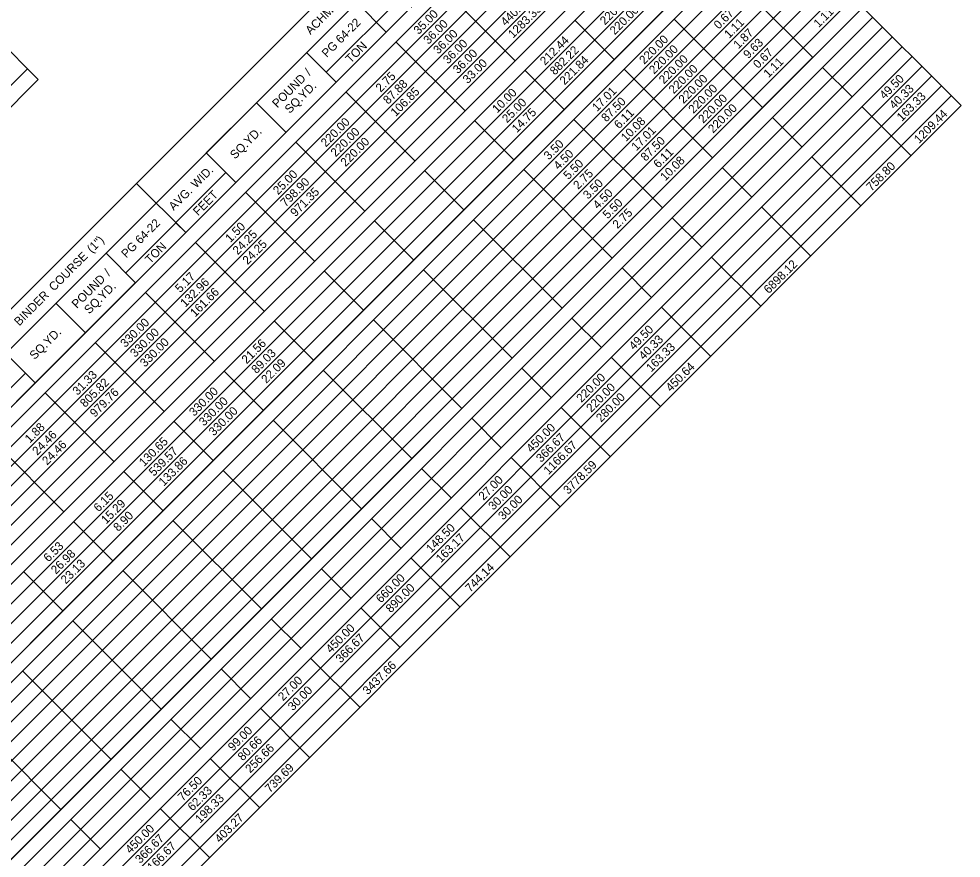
# Model space of a CAD drawing. Extents: x 1675667 to 1681231, y 227227 to 232694.
# Drawn here: x 1679139 to 1679800, y 230278 to 230867 of the extents above; entities that cross this region are included whole.
import ezdxf

# ---------------------------------------------------------------- set-up
doc = ezdxf.new("R2010")
doc.units = 0
doc.layers.add('Default', color=7, linetype='Continuous')

msp = doc.modelspace()

# ---------------------------------------------------------------- linework, layer by layer
at = {"layer": 'Default'}
for p, q in [((1678525.01, 230054.56), (1679538.35, 231068.14)), ((1679800.36, 230806.19), (1679538.35, 231068.14)), ((1679800.36, 230806.19), (1679538.35, 231068.14)), ((1678778.69, 230280.72), (1679552.14, 231054.36)), ((1678559.49, 230020.09), (1679572.82, 231033.68)), ((1678566.38, 230013.2), (1679579.72, 231026.78)), ((1678573.28, 230006.31), (1679586.61, 231019.89)), ((1678580.17, 229999.41), (1679593.51, 231013)), ((1678587.07, 229992.52), (1679600.4, 231006.1)), ((1678593.96, 229985.63), (1679607.3, 230999.21)), ((1678600.86, 229978.73), (1679614.2, 230992.32)), ((1678607.75, 229971.84), (1679621.09, 230985.42)), ((1678614.65, 229964.94), (1679627.99, 230978.53)), ((1678614.65, 229964.94), (1679627.99, 230978.53)), ((1678621.54, 229958.05), (1679634.88, 230971.64)), ((1678628.44, 229951.16), (1679641.78, 230964.74)), ((1678635.33, 229944.26), (1679648.67, 230957.85)), ((1678642.23, 229937.37), (1679655.57, 230950.96)), ((1678649.12, 229930.48), (1679662.46, 230944.06)), ((1678656.02, 229923.58), (1679669.36, 230937.17)), ((1678662.91, 229916.69), (1679676.25, 230930.28)), ((1678669.81, 229909.8), (1679683.15, 230923.38)), ((1678676.71, 229902.9), (1679690.04, 230916.49)), ((1678683.6, 229896.01), (1679696.94, 230909.6)), ((1678690.5, 229889.12), (1679703.83, 230902.7)), ((1679696.26, 230839.96), (1679634.2, 230902)), ((1679696.26, 230839.96), (1679634.2, 230902)), ((1678697.39, 229882.22), (1679710.73, 230895.81)), ((1679354.99, 230829.58), (1679425.3, 230899.91)), ((1678704.29, 229875.33), (1679717.62, 230888.92)), ((1679152.98, 230824.49), (1679082.99, 230894.46)), ((1679152.98, 230824.49), (1679082.99, 230894.46)), ((1679291.57, 230752.36), (1679432.2, 230893.02)), ((1678711.18, 229868.44), (1679724.52, 230882.02)), ((1679487.36, 230837.87), (1679439.09, 230886.12)), ((1679487.36, 230837.87), (1679439.09, 230886.12)), ((1679397.04, 230857.85), (1679376.36, 230878.53)), ((1678718.08, 229861.54), (1679731.41, 230875.13)), ((1679556.99, 230838.57), (1679592.15, 230873.73)), ((1679661.1, 230804.8), (1679731.41, 230875.13)), ((1678724.97, 229854.65), (1679738.31, 230868.24)), ((1679397.04, 230857.85), (1679390.15, 230864.75)), ((1679556.99, 230838.57), (1679529.41, 230866.14)), ((1679556.99, 230838.57), (1679529.41, 230866.14)), ((1679661.1, 230804.8), (1679599.04, 230866.84)), ((1679661.1, 230804.8), (1679599.04, 230866.84)), ((1678731.87, 229847.76), (1679745.2, 230861.34)), ((1678738.76, 229840.86), (1679752.1, 230854.45)), ((1679452.2, 230802.7), (1679403.94, 230850.96)), ((1679452.2, 230802.7), (1679403.94, 230850.96)), ((1678745.66, 229833.97), (1679758.99, 230847.55)), ((1678745.66, 229833.97), (1679758.99, 230847.55)), ((1679361.88, 230822.69), (1679341.2, 230843.37)), ((1678752.55, 229827.08), (1679765.89, 230840.66)), ((1679521.83, 230803.4), (1679556.99, 230838.57)), ((1678759.45, 229820.18), (1679772.78, 230833.77)), ((1678793.82, 230480.42), (1679145.39, 230832.07)), ((1679521.83, 230803.4), (1679494.25, 230830.98)), ((1679521.83, 230803.4), (1679494.25, 230830.98)), ((1679625.94, 230769.63), (1679563.89, 230831.67)), ((1679625.94, 230769.63), (1679563.89, 230831.67)), ((1679723.84, 230812.39), (1679703.15, 230833.07)), ((1679723.84, 230812.39), (1679703.15, 230833.07)), ((1678766.34, 229813.29), (1679779.68, 230826.87)), ((1678801.41, 230472.84), (1679152.98, 230824.49)), ((1678773.24, 229806.4), (1679786.57, 230819.98)), ((1679417.05, 230767.54), (1679368.78, 230815.79)), ((1679417.05, 230767.54), (1679368.78, 230815.79)), ((1678780.13, 229799.5), (1679793.47, 230813.09)), ((1678787.03, 229792.61), (1679800.36, 230806.19)), ((1679270.89, 230773.04), (1679306.04, 230808.2)), ((1679326.73, 230787.52), (1679306.04, 230808.2)), ((1679486.68, 230768.24), (1679521.83, 230803.4)), ((1679625.94, 230769.63), (1679661.1, 230804.8)), ((1679765.21, 230771.03), (1679730.73, 230805.5)), ((1679765.21, 230771.03), (1679730.73, 230805.5)), ((1679590.79, 230734.47), (1679528.73, 230796.51)), ((1679590.79, 230734.47), (1679528.73, 230796.51)), ((1679688.68, 230777.22), (1679667.99, 230797.9)), ((1679688.68, 230777.22), (1679667.99, 230797.9)), ((1679486.68, 230768.24), (1679459.1, 230795.81)), ((1679486.68, 230768.24), (1679459.1, 230795.81)), ((1679381.89, 230732.37), (1679333.62, 230780.63)), ((1679381.89, 230732.37), (1679333.62, 230780.63)), ((1679291.57, 230752.36), (1679270.89, 230773.04)), ((1679590.79, 230734.47), (1679625.94, 230769.63)), ((1679730.05, 230735.86), (1679695.57, 230770.33)), ((1679730.05, 230735.86), (1679695.57, 230770.33)), ((1679451.52, 230733.07), (1679486.68, 230768.24)), ((1679214.36, 230688.92), (1679284.68, 230759.25)), ((1679291.57, 230752.36), (1679284.68, 230759.25)), ((1679451.52, 230733.07), (1679423.94, 230760.65)), ((1679451.52, 230733.07), (1679423.94, 230760.65)), ((1679555.63, 230699.3), (1679493.57, 230761.34)), ((1679555.63, 230699.3), (1679493.57, 230761.34)), ((1679653.52, 230742.06), (1679632.84, 230762.74)), ((1679653.52, 230742.06), (1679632.84, 230762.74)), ((1679150.95, 230611.7), (1679291.57, 230752.36)), ((1679235.73, 230737.87), (1679221.94, 230751.66)), ((1679256.42, 230717.19), (1679221.94, 230751.66)), ((1679346.73, 230697.21), (1679298.47, 230745.46)), ((1679346.73, 230697.21), (1679298.47, 230745.46)), ((1679170.27, 230451.75), (1679451.52, 230733.07)), ((1679555.63, 230699.3), (1679590.79, 230734.47)), ((1679694.89, 230700.7), (1679660.42, 230735.17)), ((1679694.89, 230700.7), (1679660.42, 230735.17)), ((1679256.42, 230717.19), (1679249.52, 230724.08)), ((1679416.36, 230697.91), (1679388.78, 230725.48)), ((1679416.36, 230697.91), (1679388.78, 230725.48)), ((1679520.47, 230664.14), (1679458.42, 230726.18)), ((1679520.47, 230664.14), (1679458.42, 230726.18)), ((1679618.37, 230706.89), (1679597.68, 230727.57)), ((1679618.37, 230706.89), (1679597.68, 230727.57)), ((1679311.58, 230662.04), (1679263.31, 230710.3)), ((1679311.58, 230662.04), (1679263.31, 230710.3)), ((1679221.26, 230682.03), (1679200.57, 230702.71)), ((1679520.47, 230664.14), (1679555.63, 230699.3)), ((1679659.74, 230665.53), (1679625.26, 230700)), ((1679659.74, 230665.53), (1679625.26, 230700)), ((1679381.21, 230662.74), (1679353.63, 230690.32)), ((1679381.21, 230662.74), (1679353.63, 230690.32)), ((1679485.32, 230628.97), (1679423.26, 230691.01)), ((1679485.32, 230628.97), (1679423.26, 230691.01)), ((1679583.21, 230671.73), (1679562.52, 230692.41)), ((1679583.21, 230671.73), (1679562.52, 230692.41)), ((1679276.42, 230626.88), (1679228.15, 230675.13)), ((1679276.42, 230626.88), (1679228.15, 230675.13)), ((1679186.1, 230646.86), (1679165.42, 230667.54)), ((1679415, 230558.64), (1679520.47, 230664.14)), ((1679624.58, 230630.37), (1679590.11, 230664.84)), ((1679624.58, 230630.37), (1679590.11, 230664.84)), ((1679548.05, 230636.56), (1679527.37, 230657.24)), ((1679548.05, 230636.56), (1679527.37, 230657.24)), ((1679346.05, 230627.58), (1679318.47, 230655.15)), ((1679346.05, 230627.58), (1679318.47, 230655.15)), ((1679450.16, 230593.81), (1679388.1, 230655.85)), ((1679450.16, 230593.81), (1679388.1, 230655.85)), ((1679241.26, 230591.71), (1679193, 230639.97)), ((1679241.26, 230591.71), (1679193, 230639.97)), ((1679150.95, 230611.7), (1679130.26, 230632.38)), ((1679589.42, 230595.2), (1679554.95, 230629.67)), ((1679589.42, 230595.2), (1679554.95, 230629.67)), ((1679108.89, 230583.42), (1679144.05, 230618.59)), ((1679150.95, 230611.7), (1679144.05, 230618.59)), ((1679310.9, 230592.41), (1679283.31, 230619.98)), ((1679310.9, 230592.41), (1679283.31, 230619.98)), ((1679415, 230558.64), (1679352.95, 230620.68)), ((1679415, 230558.64), (1679352.95, 230620.68)), ((1679512.9, 230601.4), (1679492.21, 230622.08)), ((1679512.9, 230601.4), (1679492.21, 230622.08)), ((1679045.48, 230506.2), (1679150.95, 230611.7)), ((1679206.11, 230556.55), (1679157.84, 230604.8)), ((1679206.11, 230556.55), (1679157.84, 230604.8)), ((1679554.27, 230560.04), (1679519.79, 230594.5)), ((1679554.27, 230560.04), (1679519.79, 230594.5)), ((1679275.74, 230557.25), (1679248.16, 230584.82)), ((1679275.74, 230557.25), (1679248.16, 230584.82)), ((1679379.85, 230523.48), (1679317.79, 230585.52)), ((1679379.85, 230523.48), (1679317.79, 230585.52)), ((1679477.74, 230566.23), (1679457.05, 230586.91)), ((1679477.74, 230566.23), (1679457.05, 230586.91)), ((1679170.95, 230521.38), (1679122.68, 230569.64)), ((1679170.95, 230521.38), (1679122.68, 230569.64)), ((1679379.85, 230523.48), (1679415, 230558.64)), ((1679519.11, 230524.87), (1679484.64, 230559.34)), ((1679519.11, 230524.87), (1679484.64, 230559.34)), ((1679442.58, 230531.07), (1679421.9, 230551.75)), ((1679442.58, 230531.07), (1679421.9, 230551.75)), ((1679240.58, 230522.08), (1679213, 230549.65)), ((1679240.58, 230522.08), (1679213, 230549.65)), ((1679344.69, 230488.31), (1679282.63, 230550.35)), ((1679344.69, 230488.31), (1679282.63, 230550.35)), ((1679274.38, 230417.98), (1679379.85, 230523.48)), ((1679483.95, 230489.71), (1679449.48, 230524.17)), ((1679483.95, 230489.71), (1679449.48, 230524.17)), ((1679205.43, 230486.92), (1679177.85, 230514.49)), ((1679205.43, 230486.92), (1679177.85, 230514.49)), ((1679309.53, 230453.15), (1679247.48, 230515.19)), ((1679309.53, 230453.15), (1679247.48, 230515.19)), ((1679407.43, 230495.9), (1679386.74, 230516.58)), ((1679407.43, 230495.9), (1679386.74, 230516.58)), ((1679448.8, 230454.54), (1679414.32, 230489.01)), ((1679448.8, 230454.54), (1679414.32, 230489.01)), ((1679170.27, 230451.75), (1679142.69, 230479.32)), ((1679170.27, 230451.75), (1679142.69, 230479.32)), ((1679274.38, 230417.98), (1679212.32, 230480.02)), ((1679274.38, 230417.98), (1679212.32, 230480.02)), ((1679372.27, 230460.74), (1679351.59, 230481.42)), ((1679372.27, 230460.74), (1679351.59, 230481.42)), ((1679406.75, 230426.27), (1679379.17, 230453.84)), ((1679406.75, 230426.27), (1679379.17, 230453.84)), ((1678959.33, 230240.76), (1679170.27, 230451.75)), ((1679337.11, 230425.57), (1679316.43, 230446.25)), ((1679337.11, 230425.57), (1679316.43, 230446.25)), ((1679239.22, 230382.82), (1679177.16, 230444.86)), ((1679239.22, 230382.82), (1679177.16, 230444.86)), ((1679168.91, 230312.49), (1679274.38, 230417.98)), ((1679378.48, 230384.21), (1679344.01, 230418.68)), ((1679378.48, 230384.21), (1679344.01, 230418.68)), ((1679204.06, 230347.65), (1679142.01, 230409.69)), ((1679204.06, 230347.65), (1679142.01, 230409.69)), ((1679301.96, 230390.41), (1679281.27, 230411.09)), ((1679301.96, 230390.41), (1679281.27, 230411.09)), ((1679343.33, 230349.05), (1679308.85, 230383.51)), ((1679343.33, 230349.05), (1679308.85, 230383.51)), ((1679168.91, 230312.49), (1679106.85, 230374.53)), ((1679168.91, 230312.49), (1679106.85, 230374.53)), ((1679266.8, 230355.24), (1679246.12, 230375.92)), ((1679266.8, 230355.24), (1679246.12, 230375.92)), ((1679308.17, 230313.88), (1679273.7, 230348.35)), ((1679308.17, 230313.88), (1679273.7, 230348.35)), ((1679231.64, 230320.08), (1679210.96, 230340.76)), ((1679231.64, 230320.08), (1679210.96, 230340.76)), ((1679133.75, 230277.32), (1679168.91, 230312.49)), ((1679273.02, 230278.72), (1679238.54, 230313.18)), ((1679273.02, 230278.72), (1679238.54, 230313.18)), ((1679196.49, 230284.91), (1679175.8, 230305.59)), ((1679196.49, 230284.91), (1679175.8, 230305.59))]:
    msp.add_line(p, q, dxfattribs=at)

# ---------------------------------------------------------------- texts
for s, p in [('440.00', (1679480.9, 230861.64)), ('220.00', (1679550.54, 230862.34)), ('ACHM', (1679343.96, 230855.67)), ('1283.33', (1679486.14, 230853.1)), ('220.00', (1679557.43, 230855.45)), ('35.00', (1679419.81, 230855.7)), ('0.67', (1679630.35, 230859.43)), ('1.11', (1679700.39, 230860.54)), (' 64-22', (1679363.65, 230847.79)), ('36.00', (1679426.71, 230848.81)), ('1.11', (1679637.66, 230852.95)), ('36.00', (1679433.6, 230841.91)), ('220.00', (1679578.12, 230834.77)), ('1.87', (1679644.14, 230845.65)), ('PG', (1679355.44, 230839.58)), ('TON', (1679372.12, 230835.57)), ('36.00', (1679440.5, 230835.02)), ('212.44', (1679508.49, 230834.07)), ('9.63', (1679651.04, 230838.75)), ('36.00', (1679447.39, 230828.13)), ('882.22', (1679515.39, 230827.19)), ('220.00', (1679585.01, 230827.88)), ('0.67', (1679657.93, 230831.86)), ('33.00', (1679454.29, 230821.23)), ('221.84', (1679522.28, 230820.29)), ('220.00', (1679591.91, 230820.98)), ('1.11', (1679665.24, 230825.38)), (' /', (1679341.81, 230825.41)), ('2.75', (1679393.18, 230815.27)), ('220.00', (1679598.8, 230814.09)), ('POUND', (1679320.7, 230804.3)), ('87.88', (1679398.44, 230806.74)), ('220.00', (1679605.7, 230807.2)), ('49.50', (1679746.61, 230810.24)), ('SQ.YD.', (1679329.43, 230800.3)), ('106.85', (1679403.67, 230798.18)), ('10.00', (1679474.97, 230800.55)), ('17.01', (1679545.01, 230801.65)), ('220.00', (1679612.59, 230800.3)), ('40.33', (1679753.5, 230803.34)), ('25.00', (1679481.87, 230793.66)), ('87.50', (1679551.5, 230794.36)), ('220.00', (1679619.49, 230793.41)), ('163.33', (1679758.74, 230794.8)), ('14.75', (1679488.74, 230786.74)), ('6.11', (1679560.45, 230789.52)), ('220.00', (1679626.38, 230786.51)), ('1209.44', (1679770.82, 230779.3)), ('220.00', (1679354.75, 230776.83)), ('10.08', (1679565.28, 230780.56)), ('220.00', (1679361.64, 230769.94)), ('17.01', (1679572.59, 230774.08)), ('SQ.YD.', (1679291.09, 230768.31)), ('220.00', (1679368.54, 230763.04)), ('87.50', (1679579.08, 230766.78)), ('3.50', (1679511.1, 230767.73)), ('4.50', (1679517.99, 230760.84)), ('6.11', (1679588.03, 230761.94)), ('10.08', (1679592.86, 230752.99)), ('5.50', (1679524.89, 230753.95)), ('758.80', (1679737.39, 230745.86)), (' WID.', (1679262.16, 230746.28)), ('25.00', (1679321.24, 230743.31)), ('2.75', (1679531.76, 230747.03)), ('798.90', (1679326.49, 230734.77)), ('3.50', (1679538.68, 230740.16)), ('AVG.', (1679248.08, 230732.19)), ('FEET', (1679265.15, 230728.58)), ('971.35', (1679333.36, 230727.85)), ('4.50', (1679545.57, 230733.27)), ('5.50', (1679552.47, 230726.37)), ('2.75', (1679559.34, 230719.46)), (' 64-22', (1679223.02, 230707.13)), ('1.50', (1679287.73, 230709.79)), ('24.25', (1679292.95, 230701.23)), (' (1")', (1679189.15, 230700.83)), ('PG', (1679214.82, 230698.92)), ('TON', (1679231.49, 230694.91)), ('24.25', (1679299.85, 230694.34)), (' COURSE', (1679162.44, 230674.11)), ('6898.12', (1679665.43, 230673.88)), (' /', (1679201.18, 230684.75)), ('POUND', (1679180.07, 230663.64)), ('5.17', (1679252.57, 230674.62)), ('132.96', (1679256.17, 230664.43)), ('SQ.YD.', (1679188.8, 230659.64)), ('161.66', (1679263.06, 230657.54)), (' BINDER', (1679138.1, 230649.76)), ('330.00', (1679214.12, 230636.17)), ('49.50', (1679570.83, 230634.41)), ('SQ.YD.', (1679150.46, 230627.65)), ('330.00', (1679221.02, 230629.28)), ('40.33', (1679577.71, 230627.51)), ('330.00', (1679227.91, 230622.38)), ('21.56', (1679299.18, 230624.72)), ('163.33', (1679582.96, 230618.97)), ('89.03', (1679306.08, 230617.83)), ('22.09', (1679312.97, 230610.93)), ('450.64', (1679596.68, 230605.12)), ('31.33', (1679180.6, 230602.64)), ('220.00', (1679534.02, 230597.6)), ('805.82', (1679185.88, 230594.12)), ('220.00', (1679540.92, 230590.71)), ('979.76', (1679192.75, 230587.21)), ('330.00', (1679262.39, 230587.91)), ('280.00', (1679547.81, 230583.81)), ('330.00', (1679269.28, 230581.02)), ('330.00', (1679276.18, 230574.13)), ('1.88', (1679147.09, 230569.12)), ('24.46', (1679152.34, 230560.58)), ('450.00', (1679498.87, 230562.43)), ('24.46', (1679159.24, 230553.69)), ('130.65', (1679227.21, 230552.73)), ('366.67', (1679505.75, 230555.53)), ('1166.67', (1679511, 230546.99)), ('539.57', (1679234.12, 230545.85)), ('133.86', (1679241.01, 230538.95)), ('3778.59', (1679524.79, 230533.21)), ('27.00', (1679465.36, 230528.92)), ('30.00', (1679472.25, 230522.02)), ('6.15', (1679195.35, 230520.86)), ('30.00', (1679479.15, 230515.13)), ('15.29', (1679200.61, 230512.33)), ('8.90', (1679209.16, 230507.09)), ('148.50', (1679428.55, 230492.1)), ('163.17', (1679435.44, 230485.2)), ('6.53', (1679160.21, 230485.71)), ('26.98', (1679165.45, 230477.16)), ('23.13', (1679172.35, 230470.27)), ('744.14', (1679456.06, 230464.46)), ('660.00', (1679393.4, 230456.94)), ('890.00', (1679400.29, 230450.05)), ('450.00', (1679358.24, 230421.77)), ('366.67', (1679365.13, 230414.87)), ('3437.66', (1679384.14, 230392.52)), ('27.00', (1679324.73, 230388.26)), ('30.00', (1679331.63, 230381.36)), ('99.00', (1679289.57, 230353.09)), ('80.66', (1679296.46, 230346.19)), ('256.66', (1679301.71, 230337.65)), ('739.69', (1679315.5, 230323.86)), ('76.50', (1679254.42, 230317.93)), ('62.33', (1679261.3, 230311.02)), ('198.33', (1679266.55, 230302.48)), ('403.27', (1679280.34, 230288.69)), ('450.00', (1679217.61, 230281.11)), ('366.67', (1679224.5, 230274.21)), ('1166.67', (1679229.75, 230265.67))]:
    msp.add_text(s, height=6, rotation=45.00703, dxfattribs=at).set_placement(p)

doc.saveas('drawing.dxf')
